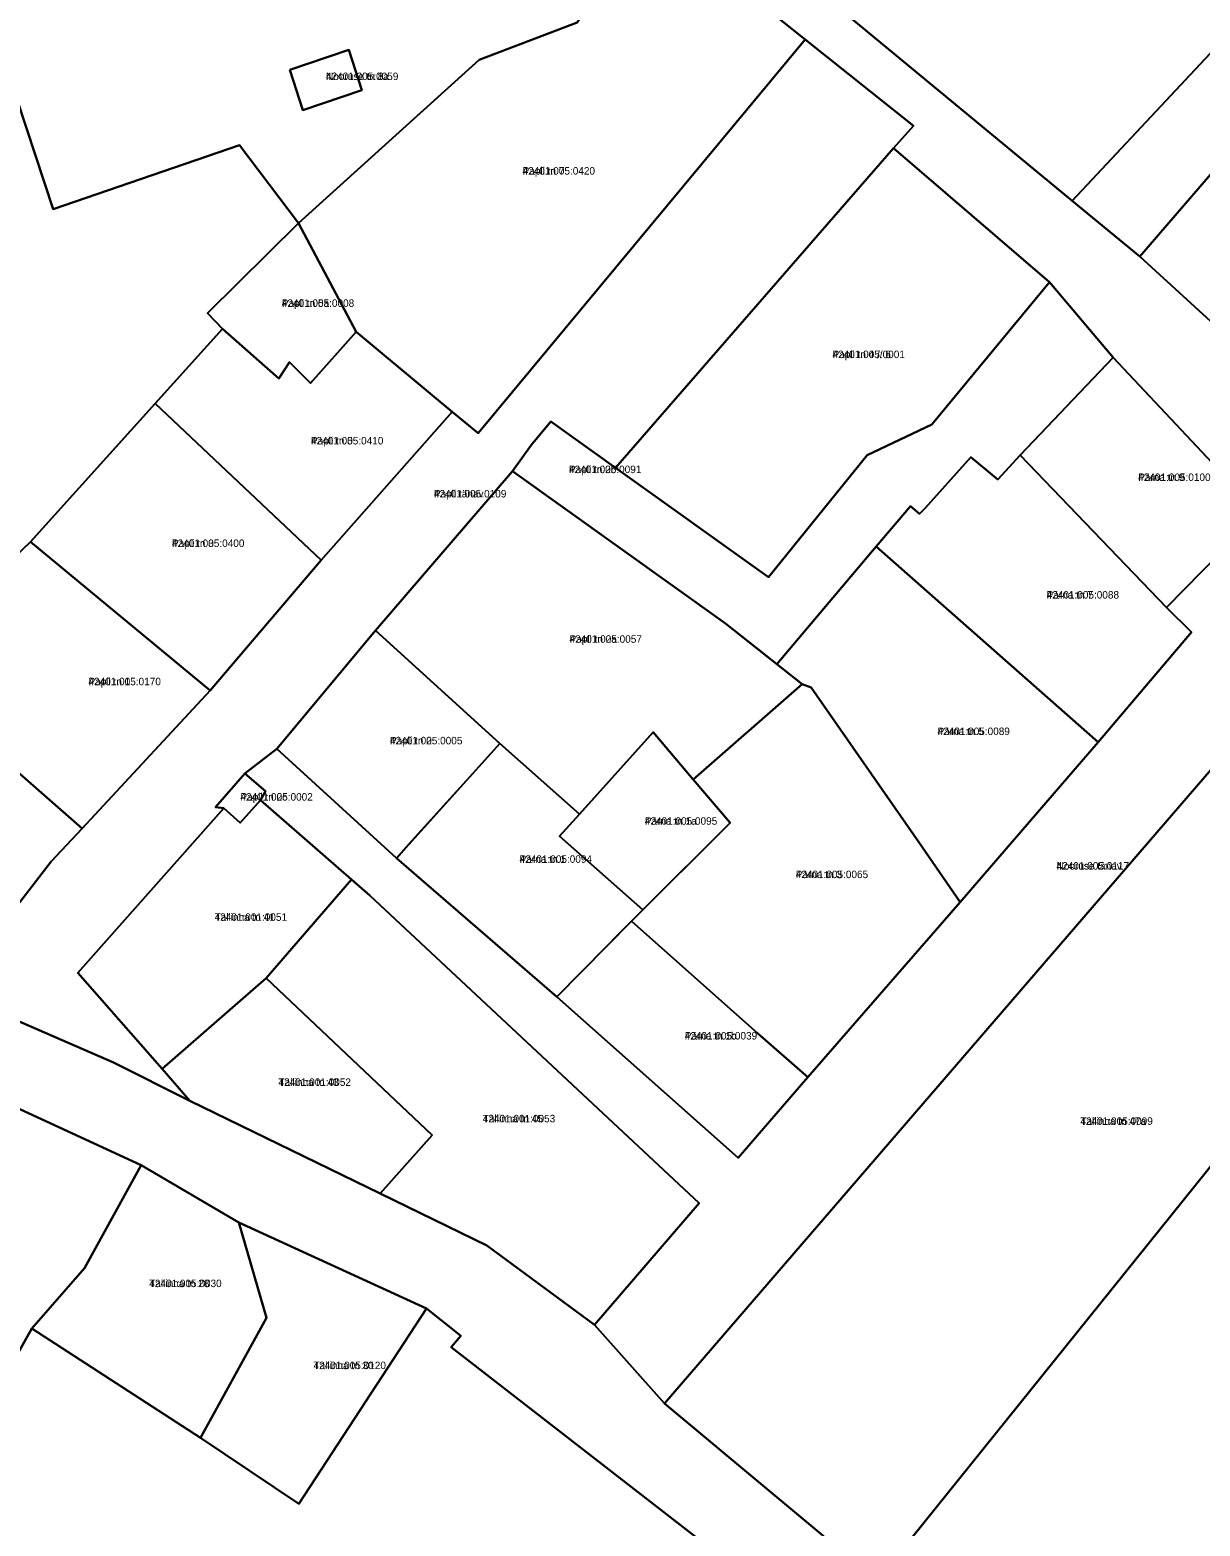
# Model space of a CAD drawing. Extents: x 595979 to 597983, y 6604231 to 6607350.
# Drawn here: x 597196.3 to 597430.6, y 6606049.7 to 6606349.2 of the extents above; entities that cross this region are included whole.
import ezdxf

# ---------------------------------------------------------------- set-up
doc = ezdxf.new("R2010")
doc.units = 0
for name, color, linetype in [('L_AADRESS', 7, 'Continuous'), ('PIIR', 7, 'Continuous'), ('TUNNUS', 7, 'Continuous')]:
    doc.layers.add(name, color=color, linetype=linetype)

msp = doc.modelspace()

# ---------------------------------------------------------------- linework, layer by layer
at = {"layer": 'PIIR'}
for points in [[(597421.94, 6606469.06), (597414.73, 6606498.88), (597440.14, 6606505.19), (597460.45, 6606510.21), (597490.98, 6606521.6), (597497.25, 6606509.28), (597526.35, 6606475.79), (597503.72, 6606456.98), (597525.56, 6606431.86), (597544.98, 6606446.72), (597555.81, 6606443.42), (597479.92, 6606388.47), (597432.66, 6606344.54), (597405, 6606315.04), (597308.82, 6606394.53), (597342.93, 6606406.67), (597352.48, 6606403.76), (597355.41, 6606401.16), (597363.55, 6606385.72), (597374.14, 6606395), (597420.74, 6606446.26), (597422.14, 6606461.42)], [(597080.06, 6606377.03), (597162.42, 6606404.24), (597160.2, 6606410.55), (597171.57, 6606414.32), (597187.46, 6606362.63), (597186.67, 6606356.79), (597201.01, 6606313.35), (597238.31, 6606326.16), (597250.13, 6606310.53), (597231.9, 6606292.55), (597234.92, 6606289.4), (597221.43, 6606274.46), (597196.48, 6606246.74), (597188.4, 6606239.05), (597174.43, 6606329.25), (597132.04, 6606321.84), (597126.69, 6606355.35), (597083.62, 6606351.85)], [(597186.67, 6606356.79), (597296.9, 6606391.91), (597320.66, 6606372.05), (597305.91, 6606350.72), (597286.26, 6606343.26), (597250.13, 6606310.53), (597238.31, 6606326.16), (597201.01, 6606313.35)], [(597261.65, 6606288.8), (597250.13, 6606310.53), (597286.26, 6606343.26), (597305.91, 6606350.72), (597320.66, 6606372.05), (597351.53, 6606347.3), (597286.06, 6606268.5), (597280.89, 6606272.79)], [(597248.4, 6606341.24), (597251.01, 6606333.19), (597262.81, 6606337.2), (597260.21, 6606345.24)], [(597248.4, 6606341.24), (597260.21, 6606345.24), (597262.81, 6606337.2), (597251.01, 6606333.19)], [(597418.56, 6606303.86), (597443.12, 6606332.4), (597475.43, 6606304.6), (597449.96, 6606275.13)], [(597369.25, 6606325.59), (597400.46, 6606298.74), (597376.89, 6606270.26), (597363.94, 6606264.12), (597344.22, 6606239.68), (597313.57, 6606261.56)], [(597231.9, 6606292.55), (597250.13, 6606310.53), (597261.65, 6606288.8), (597252.55, 6606278.54), (597248.34, 6606282.72), (597246.19, 6606279.47), (597234.92, 6606289.4)], [(597020.14, 6606291.3), (597042.44, 6606307.62), (597095.88, 6606270.34), (597144.75, 6606237.64), (597174.17, 6606217.61), (597184.95, 6606218.63), (597185.55, 6606207.91), (597206.83, 6606189.31), (597200.61, 6606182.75), (597193.69, 6606173.74), (597175.79, 6606203.2), (597166.08, 6606215.39), (597147.91, 6606228.72), (597116.23, 6606207.98), (597106.96, 6606216.02), (597128.2, 6606242.38), (597101.7, 6606260.14), (597085.57, 6606270.92), (597051.85, 6606292.26), (597044.2, 6606294.68), (597034.37, 6606292.71), (597023.9, 6606287.2)], [(597292.97, 6606260.87), (597296.7, 6606266.1), (597300.64, 6606270.83), (597313.57, 6606261.56), (597344.22, 6606239.68), (597363.94, 6606264.12), (597376.89, 6606270.26), (597400.46, 6606298.74), (597413.23, 6606283.67), (597394.62, 6606264.1), (597390.15, 6606259.19), (597384.75, 6606263.67), (597375.55, 6606253.51), (597374.46, 6606252.32), (597372.62, 6606253.88), (597365.78, 6606245.79), (597345.9, 6606222.27), (597335.57, 6606230.42)], [(597221.43, 6606274.46), (597234.92, 6606289.4), (597246.19, 6606279.47), (597248.34, 6606282.72), (597252.55, 6606278.54), (597261.65, 6606288.8), (597280.89, 6606272.79), (597254.63, 6606243.09)], [(597413.23, 6606283.67), (597441.43, 6606253.64), (597441.82, 6606251.9), (597423.91, 6606233.57), (597394.62, 6606264.1)], [(597196.48, 6606246.74), (597221.43, 6606274.46), (597254.63, 6606243.09), (597232.45, 6606216.97)], [(597372.62, 6606253.88), (597374.46, 6606252.32), (597375.55, 6606253.51), (597384.75, 6606263.67), (597390.15, 6606259.19), (597394.62, 6606264.1), (597423.91, 6606233.57), (597428.88, 6606228.62), (597410.18, 6606206.65), (597365.78, 6606245.79)], [(597265.53, 6606229), (597292.97, 6606260.87), (597335.57, 6606230.42), (597350.94, 6606218.26), (597329.14, 6606199.14), (597321.14, 6606208.61), (597306.38, 6606192.18), (597290.44, 6606206.36)], [(597188.4, 6606239.05), (597196.48, 6606246.74), (597232.45, 6606216.97), (597206.83, 6606189.31), (597185.49, 6606207.93), (597184.91, 6606218.64), (597184.43, 6606225.56)], [(597365.78, 6606245.79), (597410.18, 6606206.65), (597382.55, 6606174.56), (597374.28, 6606186.6), (597352.73, 6606217.6), (597350.94, 6606218.26), (597345.9, 6606222.27)], [(597265.53, 6606229), (597290.44, 6606206.36), (597269.72, 6606183.38), (597245.8, 6606205.26)], [(597329.14, 6606199.14), (597350.94, 6606218.26), (597352.73, 6606217.6), (597374.28, 6606186.6), (597382.55, 6606174.56), (597352.11, 6606139.54), (597341.99, 6606148.33), (597316.77, 6606170.78), (597336.51, 6606190.45)], [(597442.87, 6606212.74), (597489.89, 6606169.48), (597453.56, 6606148.67), (597452.77, 6606147.89), (597450.68, 6606145.57), (597451.19, 6606145.11), (597448.87, 6606142.54), (597445.63, 6606138.93), (597446.17, 6606138.41), (597365.99, 6606038.68), (597323.41, 6606074.19)], [(597321.14, 6606208.61), (597329.14, 6606199.14), (597336.51, 6606190.45), (597319.03, 6606173.03), (597302.39, 6606187.78), (597306.38, 6606192.18)], [(597290.44, 6606206.36), (597306.38, 6606192.18), (597302.39, 6606187.78), (597319.03, 6606173.03), (597316.77, 6606170.78), (597313.92, 6606167.9), (597311.83, 6606165.78), (597301.82, 6606155.61), (597269.72, 6606183.38), (597272.13, 6606186.14), (597284.39, 6606199.7)], [(597233.48, 6606193.59), (597239.39, 6606200.36), (597243.49, 6606196.84), (597242.53, 6606194.99), (597238.45, 6606190.47), (597235.19, 6606193.43)], [(597243.67, 6606159.38), (597222.8, 6606141.24), (597205.92, 6606160.43), (597235.19, 6606193.43), (597238.45, 6606190.47), (597242.53, 6606194.99), (597260.71, 6606179.13)], [(597287.79, 6606105.82), (597266.49, 6606116.22), (597276.87, 6606127.91), (597243.67, 6606159.38), (597260.71, 6606179.13), (597264.42, 6606175.9), (597330.35, 6606114.32), (597309.39, 6606089.95)], [(597316.77, 6606170.78), (597341.99, 6606148.33), (597352.11, 6606139.54), (597338.14, 6606123.37), (597301.82, 6606155.61)], [(597276.87, 6606127.91), (597266.49, 6606116.22), (597228.39, 6606134.83), (597222.8, 6606141.24), (597243.67, 6606159.38)], [(597452.77, 6606147.89), (597453.56, 6606148.67), (597503.14, 6606104.38), (597508.49, 6606106.92), (597528.5, 6606116.72), (597541.59, 6606123.09), (597550.67, 6606127.51), (597561.12, 6606105.01), (597587.91, 6606081.73), (597565.06, 6606039.67), (597437.08, 6605976.43), (597365.99, 6606038.68), (597446.17, 6606138.41), (597445.63, 6606138.93), (597448.87, 6606142.54), (597451.19, 6606145.11), (597450.68, 6606145.57)], [(597177.93, 6606140.7), (597218.63, 6606121.93), (597207.27, 6606101.31), (597196.74, 6606089.23), (597189.92, 6606077.21), (597151.41, 6606109.53)], [(597218.63, 6606121.93), (597238.19, 6606110.46), (597243.72, 6606091.38), (597230.52, 6606067.35), (597196.74, 6606089.23), (597207.27, 6606101.31)], [(597238.19, 6606110.46), (597275.71, 6606093.22), (597250.21, 6606054.1), (597230.52, 6606067.35), (597243.72, 6606091.38)]]:
    msp.add_lwpolyline(points, close=True, dxfattribs=at)
for points in [[(597441.43, 6606253.64), (597413.23, 6606283.67), (597400.46, 6606298.74), (597369.25, 6606325.59), (597373.25, 6606330.04), (597351.53, 6606347.3), (597320.66, 6606372.05), (597296.9, 6606391.91), (597186.67, 6606356.79), (597187.46, 6606362.63), (597244.31, 6606380.13), (597284.55, 6606394.16), (597277.83, 6606420.62), (597261.05, 6606466.64), (597252.65, 6606493), (597267.39, 6606497.51), (597276.42, 6606470.77), (597290.63, 6606426.26), (597303.29, 6606392.45), (597308.82, 6606394.53), (597405, 6606315.04), (597418.56, 6606303.86), (597449.96, 6606275.13)], [(597335.48, 6606042.99), (597280.71, 6606085.45), (597282.61, 6606087.75), (597275.71, 6606093.22), (597238.19, 6606110.46), (597218.63, 6606121.93), (597177.93, 6606140.7), (597164.82, 6606146.62), (597140.63, 6606166.31), (597143.65, 6606169.64), (597122.43, 6606187.25), (597115.38, 6606188.24), (597077.86, 6606221.72), (597054.46, 6606238.34), (597030.62, 6606259.83), (597027.93, 6606264.63), (597023.69, 6606268.92), (597012.28, 6606280.57), (596992.17, 6606301.13), (596970.33, 6606323.53), (596967.59, 6606326.51), (596937.54, 6606358.48), (596909.1, 6606385.61), (596872.46, 6606418.2)], [(597193.69, 6606173.74), (597200.61, 6606182.75), (597206.83, 6606189.31), (597232.45, 6606216.97), (597254.63, 6606243.09), (597280.89, 6606272.79), (597286.06, 6606268.5), (597351.53, 6606347.3), (597373.25, 6606330.04), (597369.25, 6606325.59), (597313.57, 6606261.56), (597300.64, 6606270.83), (597296.7, 6606266.1), (597292.97, 6606260.87), (597265.53, 6606229), (597245.8, 6606205.26), (597239.39, 6606200.36), (597233.48, 6606193.59), (597235.19, 6606193.43), (597205.92, 6606160.43), (597222.8, 6606141.24), (597228.39, 6606134.83), (597213.06, 6606142.48), (597190.5, 6606152.27)], [(597443.12, 6606332.4), (597418.56, 6606303.86), (597405, 6606315.04), (597432.66, 6606344.54)], [(597442.87, 6606212.74), (597323.41, 6606074.19), (597309.39, 6606089.95), (597330.35, 6606114.32), (597264.42, 6606175.9), (597260.71, 6606179.13), (597242.53, 6606194.99), (597243.49, 6606196.84), (597239.39, 6606200.36), (597245.8, 6606205.26), (597269.72, 6606183.38), (597301.82, 6606155.61), (597338.14, 6606123.37), (597352.11, 6606139.54), (597382.55, 6606174.56), (597410.18, 6606206.65), (597428.88, 6606228.62), (597423.91, 6606233.57), (597441.82, 6606251.9)], [(597190.5, 6606152.27), (597213.06, 6606142.48), (597228.39, 6606134.83), (597266.49, 6606116.22), (597287.79, 6606105.82), (597309.39, 6606089.95), (597323.41, 6606074.19), (597365.99, 6606038.68)], [(597179.95, 6606036.42), (597185.75, 6606055.52), (597191.64, 6606076.17), (597189.92, 6606077.21), (597196.74, 6606089.23), (597230.52, 6606067.35), (597250.21, 6606054.1), (597275.71, 6606093.22), (597282.61, 6606087.75), (597280.71, 6606085.45), (597335.48, 6606042.99)]]:
    msp.add_lwpolyline(points, dxfattribs=at)

# ---------------------------------------------------------------- texts
at = {"layer": 'L_AADRESS'}
for s, p in [('Nooruse tn 8a', (597255.61, 6606339.21)), ('Papli tn 7', (597294.98, 6606320.28)), ('Papli tn 5a', (597246.77, 6606293.79)), ('Papli tn 4 // 6', (597357.02, 6606283.53)), ('Papli tn 5', (597252.61, 6606266.24)), ('Papli tn 2b', (597304.26, 6606260.5)), ('Pärna tn 9', (597418.22, 6606258.93)), ('Papli tänav', (597277.23, 6606255.63)), ('Papli tn 3', (597224.79, 6606245.71)), ('Pärna tn 7', (597399.89, 6606235.38)), ('Papli tn 2a', (597304.37, 6606226.53)), ('Papli tn 1', (597208.06, 6606218.02)), ('Papli tn 2', (597268.43, 6606206.19)), ('Pärna tn 5', (597378.04, 6606208.05)), ('Papli tn 2c', (597238.48, 6606194.92)), ('Pärna tn 1a', (597319.45, 6606190.09)), ('Pärna tn 1', (597294.38, 6606182.46)), ('Pärna tn 3', (597349.66, 6606179.4)), ('Nooruse tänav', (597401.89, 6606181.11)), ('Tallinna tn 41', (597233.32, 6606170.85)), ('Pärna tn 1b', (597327.44, 6606147.08)), ('Tallinna tn 43', (597246.12, 6606137.8)), ('Tallinna tn 45', (597287.01, 6606130.5)), ('Tallinna tn 47a', (597406.65, 6606129.99)), ('Tallinna tn 28', (597220.23, 6606097.5)), ('Tallinna tn 30', (597253.12, 6606081.08))]:
    msp.add_text(s, height=1.5, dxfattribs=at).set_placement(p)
at = {"layer": 'TUNNUS'}
for s, p in [('42401:005:0059', (597255.61, 6606339.21)), ('42401:005:0420', (597294.98, 6606320.28)), ('42401:005:0008', (597246.77, 6606293.79)), ('42401:005:0001', (597357.02, 6606283.53)), ('42401:005:0410', (597252.61, 6606266.24)), ('42401:005:0091', (597304.26, 6606260.5)), ('42401:005:0100', (597418.22, 6606258.93)), ('42401:005:0109', (597277.23, 6606255.63)), ('42401:005:0400', (597224.79, 6606245.71)), ('42401:005:0088', (597399.89, 6606235.38)), ('42401:005:0057', (597304.37, 6606226.53)), ('42401:005:0170', (597208.06, 6606218.02)), ('42401:005:0005', (597268.43, 6606206.19)), ('42401:005:0089', (597378.04, 6606208.05)), ('42401:005:0002', (597238.48, 6606194.92)), ('42401:005:0095', (597319.45, 6606190.09)), ('42401:005:0094', (597294.38, 6606182.46)), ('42401:005:0065', (597349.66, 6606179.4)), ('42401:005:0117', (597401.89, 6606181.11)), ('42401:001:0051', (597233.32, 6606170.85)), ('42401:005:0039', (597327.44, 6606147.08)), ('42401:001:0052', (597246.12, 6606137.8)), ('42401:001:0053', (597287.01, 6606130.5)), ('42401:005:0099', (597406.65, 6606129.99)), ('42401:005:0030', (597220.23, 6606097.5)), ('42401:005:0120', (597253.12, 6606081.08))]:
    msp.add_text(s, height=1.5, dxfattribs=at).set_placement(p)

doc.saveas('drawing.dxf')
